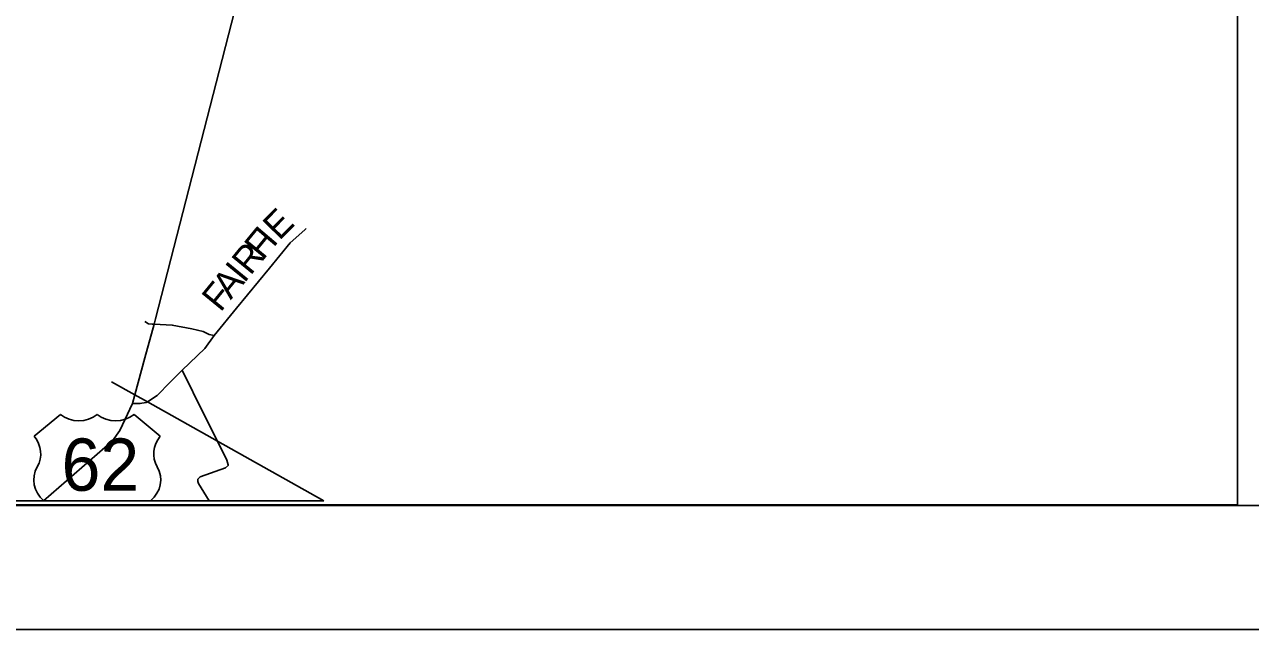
# Model space of a CAD drawing. Extents: x 0 to 784, y 0 to 440.
# Drawn here: x 367.9 to 466.8, y 0 to 48.8 of the extents above; entities that cross this region are included whole.
import ezdxf

# ---------------------------------------------------------------- set-up
doc = ezdxf.new("R2010")
doc.units = 0
for name, color, linetype in [('Default', 7, 'Continuous'), ('SH_Border', 7, 'Continuous'), ('SH_Cut_Line', 7, 'Continuous')]:
    doc.layers.add(name, color=color, linetype=linetype)

msp = doc.modelspace()

# ---------------------------------------------------------------- linework, layer by layer
at = {"layer": 'Default'}
for p, q in [((370.764, 17.349), (368.642, 15.591)), ((378.827, 15.591), (376.705, 17.349)), ((392.022, 10.383), (128.622, 10.383)), ((369.422, 10.383), (378.047, 10.383))]:
    msp.add_line(p, q, dxfattribs=at)
msp.add_lwpolyline([(31.327, 429.991), (465.774, 429.991), (465.774, 10.05), (31.327, 10.05)], close=True, dxfattribs=at)
for points in [[(377.579, 21.914), (378.324, 24.635), (378.441, 25.061), (385.064, 50.848)], [(379.618, 19.953), (379.746, 20.085), (379.926, 20.256), (380.578, 20.922), (382.428, 22.675), (383.186, 23.729), (384.966, 25.921), (387.65, 29.166), (389.312, 31.2), (390.481, 32.264), (390.598, 32.353)], [(377.579, 24.859), (377.87, 24.658), (378.174, 24.643)], [(378.174, 24.643), (378.184, 24.642), (378.324, 24.635), (379.795, 24.562), (381.381, 24.262), (382.276, 24.038), (382.76, 23.817), (383.186, 23.729)], [(369.41, 10.383), (374.96, 15.218), (375.57, 16.052), (376.576, 18.251), (376.766, 18.946), (377.579, 21.914)], [(384.314, 13.292), (384.202, 13.662), (383.433, 15.204), (382.346, 17.385), (380.578, 20.922)], [(374.889, 20), (376.766, 18.946), (377.784, 18.374), (383.433, 15.204), (392.022, 10.383)], [(376.576, 18.251), (377.186, 18.237), (377.676, 18.331), (377.784, 18.374), (378.571, 18.88), (379.618, 19.953)], [(382.77, 10.383), (381.911, 11.777), (381.86, 11.946), (381.86, 12.143), (382.047, 12.312), (384.1, 13.043), (384.321, 13.268), (384.314, 13.292)]]:
    msp.add_lwpolyline(points, dxfattribs=at)
for centre, major_axis, start_param, end_param in [((372.249, 18.604), (2.122, 0), 3.936991, 5.487786), ((375.22, 18.604), (2.122, 0), 3.936991, 5.487786), ((366.208, 14.179), (2.971, 0), 5.838949, 6.894067), ((381.261, 14.179), (-2.971, 0), 5.672304, 6.727422), ((371.58, 12.075), (2.971, 0), 2.702327, 3.899471), ((375.89, 12.075), (2.971, 0), 5.525307, 6.722451)]:
    msp.add_ellipse(centre, major_axis=major_axis, ratio=0.82844, start_param=start_param, end_param=end_param, dxfattribs=at)
at = {"layer": 'SH_Border'}
msp.add_lwpolyline([(30, 430), (670, 430), (670, 10), (30, 10)], close=True, dxfattribs=at)
at = {"layer": 'SH_Cut_Line'}
msp.add_lwpolyline([(0, 0), (680, 0), (680, 440), (0, 440)], close=True, dxfattribs=at)

# ---------------------------------------------------------------- texts
at = {"layer": 'Default'}
for s, height, rotation, p in [('E', 2.122, 45.28435, (388.427, 31.335)), ('F', 2.149, 50.64916, (387.107, 29.744)), ('I', 2.145, 49.67937, (387.934, 30.752)), ('R', 2.149, 50.74873, (386.097, 28.508)), ('A', 2.149, 50.74537, (384.509, 26.564)), ('I', 2.149, 50.7475, (385.592, 27.889)), ('F', 2.149, 50.74651, (383.679, 25.548))]:
    msp.add_text(s, height=height, rotation=rotation, dxfattribs=at).set_placement(p)
msp.add_text('62', height=4.219, dxfattribs=at).set_placement((370.852, 11.196))

doc.saveas('drawing.dxf')
